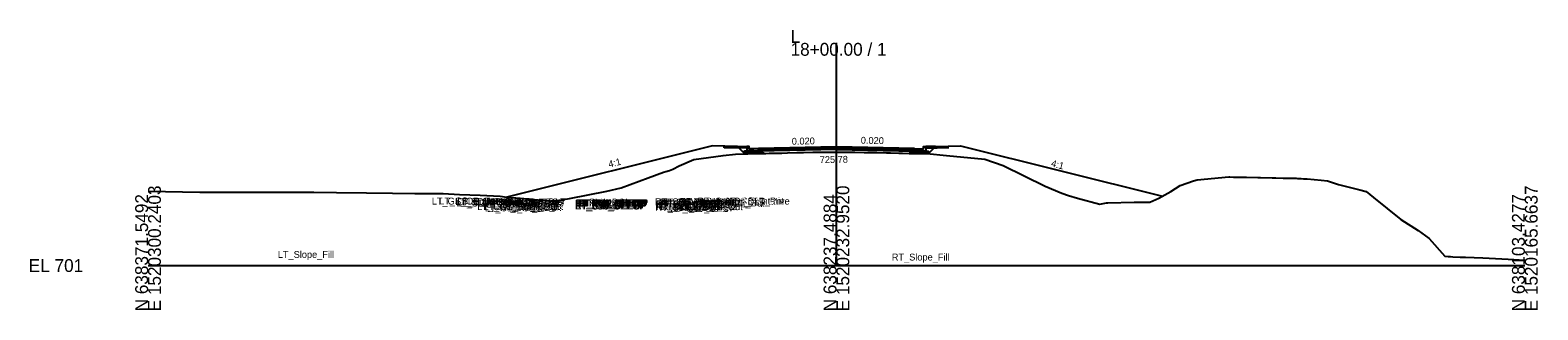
# Model space of a CAD drawing. Extents: x -26 to 3903, y -10 to 9531.
# Drawn here: x -25.7 to 302.8, y 7990.3 to 8051.4 of the extents above; entities that cross this region are included whole.
import ezdxf

# ---------------------------------------------------------------- set-up
doc = ezdxf.new("R2010")
doc.units = 0
for name, color, linetype in [('Default', 7, 'Continuous'), ('Exist Cross Section Cell', 7, 'Continuous'), ('Exist XS Center Line Elevation Label', 7, 'Continuous'), ('Exist XS Ground Line', 7, 'Continuous'), ('Old_Level_63', 7, 'Continuous'), ('Prop CMT Conc Surface', 7, 'Continuous'), ('Prop CMT Pvmt Course 1', 7, 'Continuous'), ('Prop CMT Pvmt Course 1 CG', 7, 'Continuous'), ('Prop CMT Pvmt Course 2', 7, 'Continuous'), ('Prop CMT Pvmt Course 3', 7, 'Continuous'), ('Prop CMT Pvmt Surface', 7, 'Continuous'), ('Prop CMT Slope Grass', 7, 'Continuous'), ('Prop CMT Subgrade Earthwork', 7, 'Continuous'), ('Prop XS Finish Grade Concrete', 7, 'Continuous'), ('Prop XS SE Text', 7, 'Continuous'), ('Prop XS Side Slope Text', 7, 'Continuous')]:
    doc.layers.add(name, color=color, linetype=linetype)

msp = doc.modelspace()

# ---------------------------------------------------------------- linework, layer by layer
at = {"layer": 'Exist Cross Section Cell'}
for p, q in [((150, 8000), (150, 8048.63)), ((0, 8000), (150, 8000)), ((150, 8000), (300, 8000))]:
    msp.add_line(p, q, dxfattribs=at)
at = {"layer": 'Exist XS Ground Line'}
msp.add_lwpolyline([(0, 8016.21), (11.28, 8016.03), (15.18, 8016.02), (17.69, 8016.01), (25.28, 8016.02), (28.01, 8016), (36.12, 8016.01), (41.09, 8015.99), (47.62, 8015.88), (53.25, 8015.79), (58.13, 8015.72), (59.43, 8015.7), (64.29, 8015.71), (67.83, 8015.54), (72.37, 8015.35), (76.69, 8015.12), (78.21, 8014.92), (81.09, 8014.68), (88.11, 8014.03), (91.81, 8014.62), (99.95, 8016.23), (103.06, 8016.98), (108.97, 8019.18), (112.28, 8020.4), (112.8, 8020.55), (113.6, 8020.73), (114.33, 8021.05), (115.76, 8021.81), (118.91, 8023.14), (125.32, 8024.02), (127.98, 8024.35), (130.69, 8024.41), (133.31, 8024.45), (133.83, 8024.46), (134.42, 8024.49), (134.63, 8024.5), (135.36, 8024.51), (136.47, 8024.53), (138.12, 8024.58), (139.3, 8024.61), (141.35, 8024.66), (142.08, 8024.67), (142.82, 8024.69), (144.87, 8024.73), (146.91, 8024.75), (147.66, 8024.76), (149.72, 8024.79), (149.77, 8024.79), (149.87, 8024.79), (152.48, 8024.77), (153, 8024.77), (153.25, 8024.76), (154.04, 8024.75), (156.04, 8024.72), (158.03, 8024.68), (158.83, 8024.67), (160.9, 8024.65), (161.45, 8024.64), (161.77, 8024.62), (163.61, 8024.57), (164.16, 8024.55), (164.43, 8024.54), (165.88, 8024.5), (166.65, 8024.49), (167.08, 8024.48), (167.79, 8024.47), (168.8, 8024.45), (169.73, 8024.45), (173.97, 8024.04), (182.3, 8023.25), (186.31, 8021.86), (195.51, 8017.31), (199.11, 8015.83), (200.57, 8015.33), (202.51, 8014.71), (207.39, 8013.37), (208.84, 8013.68), (209.12, 8013.72), (214.87, 8013.81), (218.31, 8013.86), (220.26, 8014.7), (222.9, 8016.15), (224.93, 8017.46), (227.8, 8018.47), (228.57, 8018.75), (235.52, 8019.34), (235.71, 8019.35), (235.75, 8019.35), (236.52, 8019.33), (236.67, 8019.33), (236.73, 8019.33), (239.35, 8019.29), (241.85, 8019.24), (242.12, 8019.24), (242.41, 8019.23), (244.92, 8019.17), (245.74, 8019.15), (247.36, 8019.11), (247.73, 8019.1), (247.77, 8019.1), (250.21, 8019.05), (250.48, 8019.04), (251.28, 8018.99), (251.77, 8018.97), (252.54, 8018.94), (255.59, 8018.62), (257.01, 8018.48), (259.42, 8017.73), (264.08, 8016.52), (265.44, 8016.16), (267.01, 8014.86), (273, 8010.03), (276.77, 8007.62), (279.17, 8005.9), (282.57, 8002.04), (283.31, 8002.01), (283.83, 8002), (284.33, 8001.92), (285.91, 8001.86), (287.05, 8001.8), (290.82, 8001.66), (296.37, 8001.38), (300, 8001.16)], dxfattribs=at)
at = {"layer": 'Old_Level_63'}
msp.add_line((125.5, 8025.74), (125.5, 8026.08), dxfattribs=at)
for points in [[(130.5, 8025.64), (125.5, 8025.74)], [(130.5, 8025.98), (130.5, 8024.96), (133, 8025.01)], [(133, 8025.01), (133, 8025.6)], [(169.5, 8025.98), (169.5, 8024.96), (167, 8025.01)], [(167, 8025.01), (167, 8025.6)], [(169.5, 8025.66), (174.5, 8025.75)]]:
    msp.add_lwpolyline(points, dxfattribs=at)
at = {"layer": 'Prop CMT Conc Surface'}
for points in [[(130.5, 8025.89), (125.5, 8025.99)], [(131, 8025.38), (131, 8025.88), (130.5, 8025.88)], [(133, 8025.5), (131, 8025.38)], [(167, 8025.5), (169, 8025.38)], [(169, 8025.38), (169, 8025.88), (169.5, 8025.88)], [(169.5, 8025.89), (174.5, 8025.99)], [(80.5, 8013.89), (75.5, 8013.99)], [(81, 8013.38), (81, 8013.88), (80.5, 8013.88)], [(83, 8013.5), (81, 8013.38)], [(117, 8013.5), (119, 8013.38)], [(119, 8013.38), (119, 8013.88), (119.5, 8013.88)], [(119.5, 8013.89), (124.5, 8013.99)]]:
    msp.add_lwpolyline(points, dxfattribs=at)
at = {"layer": 'Prop CMT Pvmt Course 1'}
for q in [(133, 8025.6), (167, 8025.6)]:
    msp.add_line((150, 8025.94), q, dxfattribs=at)
for points in [[(133, 8025.35), (150, 8025.69)], [(133, 8025.6), (133, 8025.35)], [(150, 8025.69), (150, 8025.94)], [(150, 8025.69), (150, 8025.94)], [(167, 8025.35), (150, 8025.69)], [(167, 8025.6), (167, 8025.35)]]:
    msp.add_lwpolyline(points, dxfattribs=at)
msp.add_lwpolyline([(150, 8025.69), (150, 8025.81), (150, 8025.81), (150, 8025.69)], close=True, dxfattribs=at)
msp.add_lwpolyline([(150, 8025.69), (150, 8025.81), (150, 8025.81), (150, 8025.69)], close=True, dxfattribs=at)
at = {"layer": 'Prop CMT Pvmt Course 1 CG'}
for points in [[(133, 8025.01), (130, 8024.95), (129.74, 8024.7)], [(129.74, 8024.7), (133, 8024.76)], [(133, 8024.76), (133, 8025.01)], [(167, 8025.01), (170, 8024.95), (170.26, 8024.7)], [(167, 8024.76), (167, 8025.01)], [(170.26, 8024.7), (167, 8024.76)]]:
    msp.add_lwpolyline(points, dxfattribs=at)
at = {"layer": 'Prop CMT Pvmt Course 2'}
for points in [[(150, 8025.69), (133, 8025.35)], [(133, 8025.35), (133, 8025.01)], [(133, 8025.01), (134, 8025.03)], [(150, 8025.35), (150, 8025.69)], [(150, 8025.35), (150, 8025.69)], [(150, 8025.69), (167, 8025.35)], [(167, 8025.01), (166, 8025.03)], [(167, 8025.35), (167, 8025.01)]]:
    msp.add_lwpolyline(points, dxfattribs=at)
at = {"layer": 'Prop CMT Pvmt Course 3'}
for points in [[(150, 8025.35), (133, 8025.01)], [(133, 8025.01), (133, 8024.76)], [(150, 8025.1), (150, 8025.35)], [(150, 8025.35), (167, 8025.01)], [(150, 8025.1), (150, 8025.35)], [(167, 8024.76), (166, 8024.78)], [(167, 8025.01), (167, 8024.76)]]:
    msp.add_lwpolyline(points, dxfattribs=at)
at = {"layer": 'Prop CMT Pvmt Surface'}
for p, q in [((150, 8025.94), (133, 8025.6)), ((167, 8025.6), (150, 8025.94))]:
    msp.add_line(p, q, dxfattribs=at)
for points in [[(150, 8025.94), (133, 8025.6)], [(150, 8025.94), (167, 8025.6)]]:
    msp.add_lwpolyline(points, dxfattribs=at)
at = {"layer": 'Prop CMT Slope Grass'}
for p, q in [((123, 8026.13), (78.17, 8014.92)), ((177, 8026.13), (221.02, 8015.12))]:
    msp.add_line(p, q, dxfattribs=at)
for points in [[(128.43, 8026.02), (123, 8026.13)], [(171.57, 8026.02), (177, 8026.13)]]:
    msp.add_lwpolyline(points, dxfattribs=at)
at = {"layer": 'Prop CMT Subgrade Earthwork'}
for p, q in [((134, 8024.78), (134, 8024.47)), ((166, 8024.78), (166, 8024.5))]:
    msp.add_line(p, q, dxfattribs=at)
for points in [[(133, 8024.76), (129.74, 8024.7), (128.43, 8026.02)], [(134, 8024.78), (133, 8024.76)], [(166, 8024.78), (167, 8024.76)], [(167, 8024.76), (170.26, 8024.7), (171.57, 8026.02)]]:
    msp.add_lwpolyline(points, dxfattribs=at)
at = {"layer": 'Prop XS Finish Grade Concrete'}
for points in [[(128.43, 8026.02), (130.5, 8025.98)], [(133, 8025.6), (131, 8025.48), (131, 8025.98), (130.5, 8025.98)], [(167, 8025.6), (169, 8025.48), (169, 8025.98), (169.5, 8025.98)], [(171.57, 8026.02), (169.5, 8025.98)]]:
    msp.add_lwpolyline(points, dxfattribs=at)

# ---------------------------------------------------------------- texts
at = {"layer": 'Default'}
msp.add_text('-', height=0.0001, dxfattribs=at).set_placement((0, 8000))
at = {"layer": 'Exist Cross Section Cell'}
for s, p in [('L', (140, 8048.63)), ('18+00.00 / 1', (140, 8045.83)), ('EL 701', (-26, 7998.6))]:
    msp.add_text(s, height=2.8, dxfattribs=at).set_placement(p)
for s, p in [('E 1520300.2403', (2.8, 7990)), ('E 1520232.9520', (152.8, 7990)), ('E 1520165.6637', (302.8, 7990)), ('N 638371.5492', (0, 7990)), ('N 638237.4884', (150, 7990)), ('N 638103.4277', (300, 7990))]:
    msp.add_text(s, height=2.8, rotation=90, dxfattribs=at).set_placement(p)
at = {"layer": 'Exist XS Center Line Elevation Label'}
msp.add_text('725.78', height=1.5, rotation=0.8401, dxfattribs=at).set_placement((146.37, 8022.37))
at = {"layer": 'Prop CMT Conc Surface'}
for s, p in [('LT_GS_OS_Tentative', (61.82, 8013.32)), ('LT_CSLP_Pnt', (63.44, 8013.36)), ('LT_SDWK_Out_Top', (66.94, 8013.24)), ('LT_SDWK_Out_Bot', (67.12, 8012.9)), ('LT_Sub_Trench_Out_DLT', (67.4, 8013.17)), ('LT_CG1_Shelf_Out', (71.73, 8012.1)), ('LT_SDWK_In_Top', (72.8, 8013.14)), ('LT_CG_Top_BOC', (72.86, 8013.13)), ('LT_SDWK_In_Bot', (72.99, 8012.8)), ('LT_CG_Bot_BOC', (73.07, 8012.11)), ('LT_CG_Top_Face', (73.38, 8013.13)), ('LT_Sub_OEOP', (73.39, 8011.85)), ('LT_CG_Top_Gut', (73.78, 8012.63)), ('LT_PV2_OEOT', (76.62, 8012.5)), ('LT_PV3_OEOT', (76.62, 8012.16)), ('LT_Sub_OEOT', (76.65, 8011.91)), ('LT_PV1_OEOT', (76.8, 8012.75)), ('LT_CG_Bot_IE', (76.88, 8012.16)), ('RT_PV2_OEEOP', (93, 8012.84)), ('RT_PV3_OEEOP', (93, 8012.5)), ('RT_Sub_OEEOP', (93.04, 8012.25)), ('LT_PV2_OEEOP', (93.09, 8012.84)), ('LT_PV3_OEEOP', (93.09, 8012.5)), ('LT_Sub_OEEOP', (93.12, 8012.25)), ('RT_PV1_OEEOP', (93.18, 8012.96)), ('LT_PV1_OEEOP', (93.27, 8012.96)), ('RT_PV2_IEEOP', (93.57, 8012.84)), ('LT_PV2_IEEOP', (93.66, 8012.84)), ('RT_PV1_IEEOP', (93.75, 8012.96)), ('LT_PV1_IEEOP', (93.84, 8012.96)), ('PV2_PGL', (96.03, 8012.84)), ('PV1_PGL', (96.2, 8013.09)), ('RT_Sub_Trench_Out_DLT', (110.46, 8013.17)), ('RT_PV2_OEOT', (110.53, 8012.5)), ('RT_PV3_OEOT', (110.53, 8012.16)), ('RT_Sub_OEOT', (110.56, 8011.91)), ('RT_PV1_OEOT', (110.71, 8012.75)), ('RT_CG_Bot_IE', (110.79, 8012.16)), ('RT_CG_Top_Face', (111.29, 8013.13)), ('RT_CG1_Shelf_Out', (111.64, 8012.1)), ('RT_CG_Top_Gut', (111.69, 8012.63)), ('RT_SDWK_In_Top', (111.71, 8013.14)), ('RT_CG_Top_BOC', (111.77, 8013.13)), ('RT_SDWK_In_Bot', (111.9, 8012.8)), ('RT_CG_Bot_BOC', (111.98, 8012.11)), ('RT_Sub_OEOP', (113.81, 8011.85)), ('RT_SDWK_Out_Top', (115.85, 8013.24)), ('RT_SDWK_Out_Bot', (116.03, 8012.9)), ('RT_GS_OS_Tentative', (119.75, 8013.32)), ('RT_CSLP_Pnt', (125.37, 8013.36)), ('LT_Slope_Fill', (28.27, 8001.67)), ('RT_Slope_Fill', (162.06, 8001.1))]:
    msp.add_text(s, height=1.5, dxfattribs=at).set_placement(p)
at = {"layer": 'Prop XS SE Text'}
for rotation, p in [(1.1458, (140.28, 8026.38)), (358.8542, (155.3, 8026.62))]:
    msp.add_text('0.020', height=1.5, rotation=rotation, dxfattribs=at).set_placement(p)
at = {"layer": 'Prop XS Side Slope Text'}
for rotation, p in [(14.0362, (100.49, 8021.37)), (344.7445, (196.66, 8021.69))]:
    msp.add_text('4:1', height=1.5, rotation=rotation, dxfattribs=at).set_placement(p)

doc.saveas('drawing.dxf')
